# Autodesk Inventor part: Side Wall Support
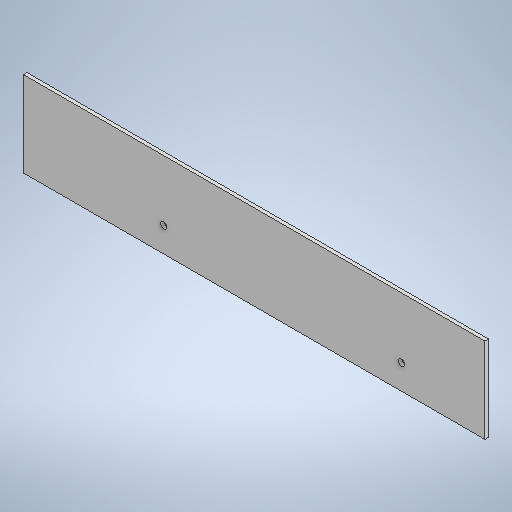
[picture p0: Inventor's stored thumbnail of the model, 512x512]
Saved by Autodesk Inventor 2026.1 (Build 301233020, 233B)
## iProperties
Created: 2026-10
Part Number: Side Wall Support
Material: Generic
Document SubType Name: Modeling
Designer: hp
Density: 1 g/cm^3
Appearance: Default
Author: hp
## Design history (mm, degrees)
sketch "Sketch1"
  geometry: L1 (0, 0)-(700, 0); L2 (700, 120)-(0, 120); L3 (0, 120)-(0, 0); L4 (700, 120)-(700, 0); L5 (50, 120)-(50, 0)
  constraints: 10 end point, 2 point on line, 1 horizontal, 1 parallel, 1 perpendicular, 1 vertical
  dimensions: "d28" = 700 distance of L2.start L2.end; "d29" = 120 distance of L2.end L1.start; "d48" = 50 distance between parallel lines of L3 L5
extrude "Extrusion2" new body sketch "Sketch1" distance "d23" = 5; taper "d24" = 0 deg
sketch "Sketch5"
  geometry: 2 further points
hole "Hole2" sketch "Sketch5" at (-247.5, 35), (-582.5, 35) diameter "d56" = 9; stored, may be unused: countersink angle "d60" = 90 deg, drill point angle "d62" = 0 deg; dims "d57" = 6, "d58" = 4, "d59" = 2, "d61" = 8
body "Solid2"
